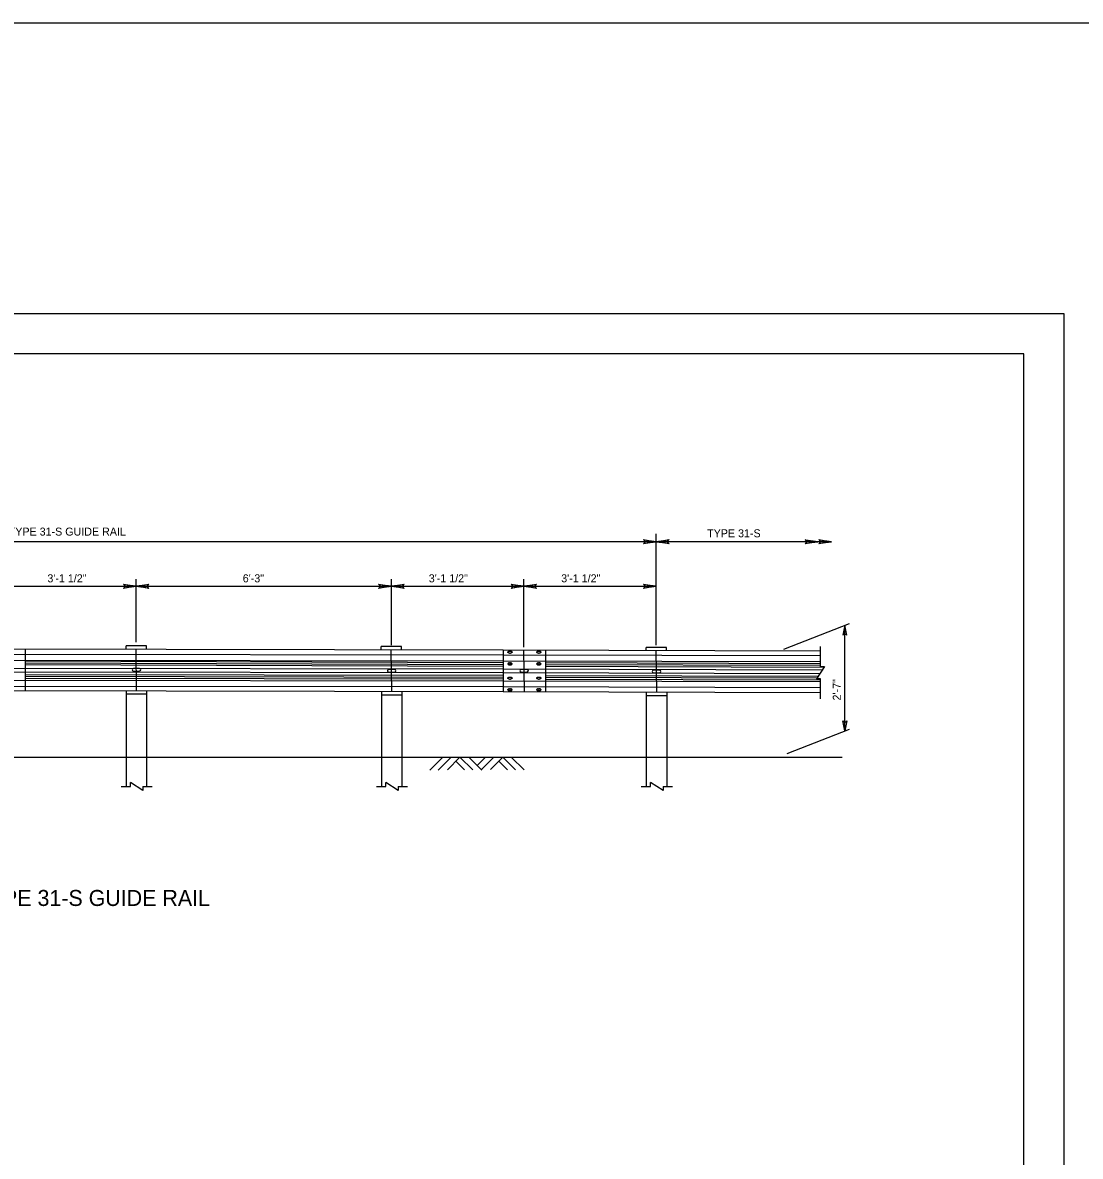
# Model space of a CAD drawing. Extents: x 637628 to 640188, y 298266 to 300751.
# Drawn here: x 639570.1 to 639966.7, y 300325.7 to 300750.7 of the extents above; entities that cross this region are included whole.
import ezdxf

# ---------------------------------------------------------------- set-up
doc = ezdxf.new("R2010")
doc.units = 0
for name, color, linetype in [('1', 7, 'Continuous'), ('2', 7, 'Continuous'), ('S-ABUT-CONC', 7, 'Continuous'), ('S-ANNO-CELL', 7, 'Continuous'), ('S-ANNO-DIMS-MANL', 7, 'Continuous'), ('S-ANNO-T120-01', 7, 'Continuous')]:
    doc.layers.add(name, color=color, linetype=linetype)

# ---------------------------------------------------------------- blocks, each defined once
blk = doc.blocks.new('LT')
at = {"layer": 'S-ANNO-DIMS-MANL'}
blk.add_lwpolyline([(0, 0), (-0.503, 0.094), (-0.464, 0.067), (-0.444, 0.034), (-0.439, 0), (-0.444, -0.034), (-0.464, -0.067), (-0.503, -0.094)], close=True, dxfattribs=at)

msp = doc.modelspace()

# ---------------------------------------------------------------- linework, layer by layer
at = {"layer": '1'}
msp.add_lwpolyline([(639119.52, 300641.58), (639960.52, 300641.58), (639960.52, 300047.58), (639119.52, 300047.58)], close=True, dxfattribs=at)
msp.add_lwpolyline([(639945.52, 300062.58), (639945.52, 300626.55), (639159.55, 300626.55), (639159.55, 300062.58), (639945.52, 300062.58), (639945.52, 300088.93), (639745.53, 300088.93), (639745.53, 300153.61), (639945.52, 300153.61), (639945.52, 300182.57), (639745.53, 300182.57), (639745.53, 300062.58), (639824.33, 300062.58), (639824.33, 300088.93), (639824.33, 300062.58), (639901.33, 300062.58), (639901.33, 300088.93), (639901.33, 300076.62), (639945.52, 300076.62)], dxfattribs=at)
at = {"layer": '2'}
for p, q in [((639727.59, 300475.23), (639722.82, 300470.46)), ((639730.7, 300475.23), (639725.92, 300470.46)), ((639734.11, 300475.36), (639729.38, 300470.63)), ((639735.77, 300470.59), (639732.55, 300473.81)), ((639738.88, 300470.59), (639734.11, 300475.36)), ((639742.29, 300470.46), (639737.56, 300475.19)), ((639743.71, 300475.33), (639740.57, 300472.18)), ((639746.82, 300475.33), (639742.05, 300470.56)), ((639750.13, 300475.36), (639745.5, 300470.73)), ((639751.9, 300470.6), (639748.68, 300473.82)), ((639754.91, 300470.59), (639750.13, 300475.36)), ((639758.15, 300470.56), (639753.35, 300475.36))]:
    msp.add_line(p, q, dxfattribs=at)
msp.add_lwpolyline([(638881.69, 300750.65), (640188.06, 300750.65), (640188.06, 299900.76), (638881.69, 299900.76)], close=True, dxfattribs=at)
for points in [[(639803.17, 300556.67), (639803.34, 300556.34), (639807.71, 300556.1), (639803.17, 300556.67), (639802.94, 300556.87), (639807.71, 300556.1), (639803.35, 300555.89), (639803.18, 300555.56), (639807.71, 300556.1), (639802.94, 300555.34), (639803.18, 300555.56)], [(639812.25, 300555.53), (639812.08, 300555.86), (639807.71, 300556.1), (639812.25, 300555.53), (639812.48, 300555.33), (639807.71, 300556.1), (639812.08, 300556.32), (639812.24, 300556.65), (639807.71, 300556.1), (639812.48, 300556.86), (639812.24, 300556.65)], [(639863.73, 300556.65), (639863.89, 300556.32), (639868.26, 300556.08), (639863.73, 300556.65), (639863.49, 300556.85), (639868.26, 300556.08), (639863.9, 300555.86), (639863.74, 300555.54), (639868.26, 300556.08), (639863.49, 300555.32), (639863.74, 300555.54)], [(639868.92, 300556.67), (639869.09, 300556.34), (639873.46, 300556.1), (639868.92, 300556.67), (639868.69, 300556.87), (639873.46, 300556.1), (639869.09, 300555.89), (639868.93, 300555.56), (639873.46, 300556.1), (639868.69, 300555.34), (639868.93, 300555.56)], [(639608.18, 300539.94), (639608.35, 300539.61), (639612.72, 300539.37), (639608.18, 300539.94), (639607.95, 300540.14), (639612.72, 300539.37), (639608.35, 300539.16), (639608.19, 300538.83), (639612.72, 300539.37), (639607.95, 300538.61), (639608.19, 300538.83)], [(639617.26, 300538.8), (639617.09, 300539.13), (639612.72, 300539.37), (639617.26, 300538.8), (639617.49, 300538.6), (639612.72, 300539.37), (639617.09, 300539.59), (639617.25, 300539.91), (639612.72, 300539.37), (639617.49, 300540.13), (639617.25, 300539.91)], [(639703.85, 300539.94), (639704.02, 300539.61), (639708.39, 300539.37), (639703.85, 300539.94), (639703.62, 300540.14), (639708.39, 300539.37), (639704.03, 300539.16), (639703.86, 300538.83), (639708.39, 300539.37), (639703.62, 300538.61), (639703.86, 300538.83)], [(639712.93, 300538.8), (639712.76, 300539.13), (639708.39, 300539.37), (639712.93, 300538.8), (639713.16, 300538.6), (639708.39, 300539.37), (639712.76, 300539.59), (639712.92, 300539.91), (639708.39, 300539.37), (639713.16, 300540.13), (639712.92, 300539.91)], [(639753.51, 300539.94), (639753.68, 300539.61), (639758.05, 300539.37), (639753.51, 300539.94), (639753.28, 300540.14), (639758.05, 300539.37), (639753.69, 300539.16), (639753.52, 300538.83), (639758.05, 300539.37), (639753.28, 300538.61), (639753.52, 300538.83)], [(639762.59, 300538.8), (639762.42, 300539.13), (639758.05, 300539.37), (639762.59, 300538.8), (639762.82, 300538.6), (639758.05, 300539.37), (639762.42, 300539.59), (639762.58, 300539.91), (639758.05, 300539.37), (639762.82, 300540.13), (639762.58, 300539.91)], [(639803.17, 300539.94), (639803.34, 300539.61), (639807.71, 300539.37), (639803.17, 300539.94), (639802.94, 300540.14), (639807.71, 300539.37), (639803.35, 300539.16), (639803.18, 300538.83), (639807.71, 300539.37), (639802.94, 300538.61), (639803.18, 300538.83)]]:
    msp.add_lwpolyline(points, dxfattribs=at)
at = {"layer": 'S-ABUT-CONC'}
for p, q in [((639807.71, 300517.3), (639807.71, 300559.09)), ((639807.71, 300556.1), (639562.85, 300556.1)), ((639873.46, 300556.1), (639807.71, 300556.1)), ((639612.72, 300518.38), (639612.72, 300542.08)), ((639708.39, 300517.88), (639708.39, 300542.08)), ((639708.39, 300517.25), (639708.39, 300542.08)), ((639758.05, 300516.51), (639758.05, 300542.08)), ((639562.85, 300539.37), (639660.56, 300539.37)), ((639660.56, 300539.37), (639708.39, 300539.37)), ((639708.39, 300539.37), (639758.05, 300539.37)), ((639758.05, 300539.37), (639807.71, 300539.37)), ((639855.56, 300515.85), (639880.18, 300525.46)), ((639878.42, 300485.14), (639878.42, 300524.77)), ((639856.74, 300476.67), (639880.18, 300485.83))]:
    msp.add_line(p, q, dxfattribs=at)
at = {"layer": 'S-ANNO-CELL'}
for p, q in [((639750.31, 300515.42), (639555.11, 300515.82)), ((639571.02, 300515.78), (639571.02, 300500.15)), ((639608.9, 300515.89), (639608.9, 300517.07)), ((639616.54, 300517.07), (639608.9, 300517.07)), ((639612.86, 300500.24), (639612.65, 300515.88)), ((639616.54, 300515.86), (639616.54, 300517.07)), ((639704.57, 300515.57), (639704.57, 300516.75)), ((639712.21, 300516.75), (639704.57, 300516.75)), ((639708.55, 300499.92), (639708.34, 300515.56)), ((639712.21, 300515.55), (639712.21, 300516.75)), ((639750.31, 300515.58), (639750.31, 300499.95)), ((639869.3, 300515.11), (639750.31, 300515.42)), ((639752.69, 300515.04), (639753.01, 300515.04)), ((639752.69, 300514.93), (639752.69, 300515.04)), ((639753.01, 300514.93), (639752.69, 300514.93)), ((639752.69, 300514.33), (639753.01, 300514.33)), ((639753.01, 300514.93), (639753.01, 300515.04)), ((639758.26, 300499.93), (639758.05, 300515.4)), ((639763.51, 300515.04), (639763.83, 300515.04)), ((639763.51, 300514.93), (639763.51, 300515.04)), ((639763.83, 300514.93), (639763.51, 300514.93)), ((639763.51, 300514.33), (639763.83, 300514.33)), ((639763.83, 300514.93), (639763.83, 300515.04)), ((639766.22, 300515.54), (639766.22, 300499.91)), ((639803.89, 300515.28), (639803.89, 300516.46)), ((639811.53, 300516.46), (639803.89, 300516.46)), ((639807.92, 300499.67), (639807.71, 300515.27)), ((639811.53, 300515.26), (639811.53, 300516.46)), ((639869.3, 300509.35), (639869.3, 300516.85)), ((639750.31, 300513.57), (639555.11, 300513.81)), ((639750.31, 300511.36), (639555.11, 300511.6)), ((639750.31, 300510.67), (639571.02, 300511.26)), ((639750.31, 300509.99), (639571.02, 300510.58)), ((639750.31, 300509.3), (639571.02, 300509.89)), ((639869.3, 300513.26), (639750.31, 300513.57)), ((639869.3, 300511.05), (639750.31, 300511.36)), ((639752.69, 300510.67), (639753.01, 300510.67)), ((639752.69, 300510.06), (639752.69, 300509.95)), ((639753.01, 300510.06), (639752.69, 300510.06)), ((639752.69, 300509.95), (639753.01, 300509.95)), ((639753.01, 300510.06), (639753.01, 300509.95)), ((639763.51, 300510.67), (639763.83, 300510.67)), ((639763.51, 300510.06), (639763.51, 300509.95)), ((639763.83, 300510.06), (639763.51, 300510.06)), ((639763.51, 300509.95), (639763.83, 300509.95)), ((639763.83, 300510.06), (639763.83, 300509.95)), ((639869.3, 300510.36), (639766.22, 300510.63)), ((639869.3, 300509.67), (639766.22, 300509.95)), ((639750.31, 300508.31), (639555.11, 300508.55)), ((639750.31, 300506.9), (639555.11, 300507.14)), ((639750.31, 300505.91), (639571.02, 300506.24)), ((639750.31, 300505.22), (639571.02, 300505.61)), ((639613.93, 300508.59), (639611.7, 300508.56)), ((639611.72, 300507.6), (639613.95, 300507.63)), ((639709.6, 300508.18), (639707.38, 300508.15)), ((639707.39, 300507.2), (639709.62, 300507.23)), ((639869.93, 300507.99), (639750.31, 300508.31)), ((639869.02, 300506.59), (639750.31, 300506.9)), ((639759.26, 300508.24), (639757.04, 300508.21)), ((639757.05, 300507.25), (639759.28, 300507.28)), ((639870.57, 300508.99), (639766.22, 300509.26)), ((639868.38, 300505.59), (639766.22, 300505.87)), ((639808.92, 300507.93), (639806.69, 300507.9)), ((639806.7, 300506.95), (639808.93, 300506.98)), ((639870.8, 300509.35), (639867.8, 300504.71)), ((639869.3, 300509.35), (639870.8, 300509.35)), ((639750.31, 300503.85), (639555.11, 300504.09)), ((639750.31, 300501.64), (639555.11, 300501.88)), ((639750.31, 300504.54), (639571.02, 300504.85)), ((639869.3, 300503.54), (639750.31, 300503.85)), ((639869.3, 300501.32), (639750.31, 300501.64)), ((639752.69, 300505.32), (639753.01, 300505.32)), ((639752.69, 300505.21), (639752.69, 300505.32)), ((639753.01, 300505.21), (639752.69, 300505.21)), ((639752.69, 300504.61), (639753.01, 300504.61)), ((639753.01, 300505.21), (639753.01, 300505.32)), ((639763.51, 300505.32), (639763.83, 300505.32)), ((639763.51, 300505.21), (639763.51, 300505.32)), ((639763.83, 300505.21), (639763.51, 300505.21)), ((639763.51, 300504.61), (639763.83, 300504.61)), ((639763.83, 300505.21), (639763.83, 300505.32)), ((639867.93, 300504.91), (639766.22, 300505.18)), ((639869.3, 300504.22), (639766.22, 300504.5)), ((639869.3, 300504.71), (639867.8, 300504.71)), ((639869.3, 300497.21), (639869.3, 300504.71)), ((639750.31, 300499.79), (639555.11, 300500.19)), ((639609.11, 300493.59), (639609.11, 300500.25)), ((639616.75, 300498.9), (639609.11, 300498.9)), ((639616.75, 300493.59), (639616.75, 300500.22)), ((639704.78, 300494.89), (639704.78, 300499.94)), ((639712.42, 300498.59), (639704.78, 300498.59)), ((639712.42, 300494.89), (639712.42, 300499.91)), ((639869.3, 300499.47), (639750.31, 300499.79)), ((639752.69, 300500.94), (639753.01, 300500.94)), ((639752.69, 300500.34), (639752.69, 300500.23)), ((639753.01, 300500.34), (639752.69, 300500.34)), ((639752.69, 300500.23), (639753.01, 300500.23)), ((639753.01, 300500.34), (639753.01, 300500.23)), ((639763.51, 300500.94), (639763.83, 300500.94)), ((639763.51, 300500.34), (639763.51, 300500.23)), ((639763.83, 300500.34), (639763.51, 300500.34)), ((639763.51, 300500.23), (639763.83, 300500.23)), ((639763.83, 300500.34), (639763.83, 300500.23)), ((639804.1, 300496.17), (639804.1, 300499.64)), ((639811.73, 300498.3), (639804.1, 300498.3)), ((639811.73, 300496.17), (639811.73, 300499.62)), ((639609.11, 300475.37), (639609.11, 300493.59)), ((639616.75, 300475.37), (639616.75, 300493.59)), ((639704.78, 300475.37), (639704.78, 300494.89)), ((639712.42, 300475.37), (639712.42, 300494.89)), ((639804.1, 300475.36), (639804.1, 300496.17)), ((639811.73, 300475.36), (639811.73, 300496.17)), ((639555.11, 300475.37), (639877.39, 300475.37)), ((639609.11, 300464.35), (639609.11, 300475.37)), ((639616.75, 300464.35), (639616.75, 300475.37)), ((639704.78, 300464.35), (639704.78, 300475.37)), ((639712.42, 300464.35), (639712.42, 300475.37)), ((639804.1, 300464.34), (639804.1, 300475.36)), ((639811.73, 300464.34), (639811.73, 300475.36)), ((639607.11, 300464.35), (639610.61, 300464.35)), ((639610.61, 300464.35), (639610.61, 300465.85)), ((639615.25, 300462.85), (639610.61, 300465.85)), ((639615.25, 300464.35), (639615.25, 300462.85)), ((639615.25, 300464.35), (639618.75, 300464.35)), ((639702.78, 300464.35), (639706.28, 300464.35)), ((639706.28, 300464.35), (639706.28, 300465.85)), ((639710.92, 300462.85), (639706.28, 300465.85)), ((639710.92, 300464.35), (639710.92, 300462.85)), ((639710.92, 300464.35), (639714.42, 300464.35)), ((639802.1, 300464.34), (639805.6, 300464.34)), ((639805.6, 300464.34), (639805.6, 300465.84)), ((639810.23, 300462.84), (639805.6, 300465.84)), ((639810.23, 300464.34), (639810.23, 300462.84)), ((639810.23, 300464.34), (639813.73, 300464.34))]:
    msp.add_line(p, q, dxfattribs=at)
for points in [[(639752.69, 300514.33), (639752.58, 300514.34), (639752.47, 300514.35), (639752.37, 300514.38), (639752.28, 300514.41), (639752.2, 300514.46), (639752.14, 300514.51), (639752.09, 300514.57), (639752.07, 300514.63), (639752.06, 300514.69), (639752.07, 300514.75), (639752.09, 300514.81), (639752.14, 300514.87), (639752.2, 300514.92), (639752.28, 300514.96), (639752.37, 300515), (639752.47, 300515.02), (639752.58, 300515.04), (639752.69, 300515.04)], [(639752.69, 300514.93), (639752.58, 300514.93), (639752.47, 300514.91), (639752.37, 300514.89), (639752.28, 300514.85), (639752.2, 300514.81), (639752.14, 300514.76), (639752.09, 300514.7), (639752.07, 300514.64), (639752.06, 300514.63)], [(639753.01, 300515.04), (639753.12, 300515.04), (639753.23, 300515.02), (639753.33, 300515), (639753.42, 300514.96), (639753.5, 300514.92), (639753.56, 300514.87), (639753.61, 300514.81), (639753.64, 300514.75), (639753.65, 300514.69), (639753.64, 300514.63), (639753.61, 300514.57), (639753.56, 300514.51), (639753.5, 300514.46), (639753.42, 300514.41), (639753.33, 300514.38), (639753.23, 300514.35), (639753.12, 300514.34), (639753.01, 300514.33)], [(639753.64, 300514.63), (639753.64, 300514.64), (639753.61, 300514.7), (639753.56, 300514.76), (639753.5, 300514.81), (639753.42, 300514.85), (639753.33, 300514.89), (639753.23, 300514.91), (639753.12, 300514.93), (639753.01, 300514.93)], [(639763.51, 300514.33), (639763.4, 300514.34), (639763.3, 300514.35), (639763.19, 300514.38), (639763.1, 300514.41), (639763.03, 300514.46), (639762.96, 300514.51), (639762.91, 300514.57), (639762.89, 300514.63), (639762.88, 300514.69), (639762.89, 300514.75), (639762.91, 300514.81), (639762.96, 300514.87), (639763.03, 300514.92), (639763.1, 300514.96), (639763.19, 300515), (639763.3, 300515.02), (639763.4, 300515.04), (639763.51, 300515.04)], [(639763.51, 300514.93), (639763.4, 300514.93), (639763.3, 300514.91), (639763.19, 300514.89), (639763.1, 300514.85), (639763.03, 300514.81), (639762.96, 300514.76), (639762.91, 300514.7), (639762.89, 300514.64), (639762.88, 300514.63)], [(639763.83, 300515.04), (639763.94, 300515.04), (639764.05, 300515.02), (639764.15, 300515), (639764.24, 300514.96), (639764.32, 300514.92), (639764.38, 300514.87), (639764.43, 300514.81), (639764.46, 300514.75), (639764.47, 300514.69), (639764.46, 300514.63), (639764.43, 300514.57), (639764.38, 300514.51), (639764.32, 300514.46), (639764.24, 300514.41), (639764.15, 300514.38), (639764.05, 300514.35), (639763.94, 300514.34), (639763.83, 300514.33)], [(639764.46, 300514.63), (639764.46, 300514.64), (639764.43, 300514.7), (639764.38, 300514.76), (639764.32, 300514.81), (639764.24, 300514.85), (639764.15, 300514.89), (639764.05, 300514.91), (639763.94, 300514.93), (639763.83, 300514.93)], [(639752.69, 300510.67), (639752.58, 300510.66), (639752.47, 300510.64), (639752.37, 300510.62), (639752.28, 300510.58), (639752.2, 300510.54), (639752.14, 300510.49), (639752.09, 300510.43), (639752.07, 300510.37), (639752.06, 300510.31), (639752.07, 300510.25), (639752.09, 300510.19), (639752.14, 300510.13), (639752.2, 300510.08), (639752.28, 300510.04), (639752.37, 300510), (639752.47, 300509.98), (639752.58, 300509.96), (639752.69, 300509.95)], [(639752.69, 300510.06), (639752.58, 300510.07), (639752.47, 300510.09), (639752.37, 300510.11), (639752.28, 300510.15), (639752.2, 300510.19), (639752.14, 300510.24), (639752.09, 300510.3), (639752.07, 300510.36), (639752.06, 300510.37)], [(639753.01, 300509.95), (639753.12, 300509.96), (639753.23, 300509.98), (639753.33, 300510), (639753.42, 300510.04), (639753.5, 300510.08), (639753.56, 300510.13), (639753.61, 300510.19), (639753.64, 300510.25), (639753.65, 300510.31), (639753.64, 300510.37), (639753.61, 300510.43), (639753.56, 300510.49), (639753.5, 300510.54), (639753.42, 300510.58), (639753.33, 300510.62), (639753.23, 300510.64), (639753.12, 300510.66), (639753.01, 300510.67)], [(639753.64, 300510.37), (639753.64, 300510.36), (639753.61, 300510.3), (639753.56, 300510.24), (639753.5, 300510.19), (639753.42, 300510.15), (639753.33, 300510.11), (639753.23, 300510.09), (639753.12, 300510.07), (639753.01, 300510.06)], [(639763.51, 300510.67), (639763.4, 300510.66), (639763.3, 300510.64), (639763.19, 300510.62), (639763.1, 300510.58), (639763.03, 300510.54), (639762.96, 300510.49), (639762.91, 300510.43), (639762.89, 300510.37), (639762.88, 300510.31), (639762.89, 300510.25), (639762.91, 300510.19), (639762.96, 300510.13), (639763.03, 300510.08), (639763.1, 300510.04), (639763.19, 300510), (639763.3, 300509.98), (639763.4, 300509.96), (639763.51, 300509.95)], [(639763.51, 300510.06), (639763.4, 300510.07), (639763.3, 300510.09), (639763.19, 300510.11), (639763.1, 300510.15), (639763.03, 300510.19), (639762.96, 300510.24), (639762.91, 300510.3), (639762.89, 300510.36), (639762.88, 300510.37)], [(639763.83, 300509.95), (639763.94, 300509.96), (639764.05, 300509.98), (639764.15, 300510), (639764.24, 300510.04), (639764.32, 300510.08), (639764.38, 300510.13), (639764.43, 300510.19), (639764.46, 300510.25), (639764.47, 300510.31), (639764.46, 300510.37), (639764.43, 300510.43), (639764.38, 300510.49), (639764.32, 300510.54), (639764.24, 300510.58), (639764.15, 300510.62), (639764.05, 300510.64), (639763.94, 300510.66), (639763.83, 300510.67)], [(639764.46, 300510.37), (639764.46, 300510.36), (639764.43, 300510.3), (639764.38, 300510.24), (639764.32, 300510.19), (639764.24, 300510.15), (639764.15, 300510.11), (639764.05, 300510.09), (639763.94, 300510.07), (639763.83, 300510.06)], [(639752.69, 300504.61), (639752.58, 300504.61), (639752.47, 300504.63), (639752.37, 300504.66), (639752.28, 300504.69), (639752.2, 300504.74), (639752.14, 300504.79), (639752.09, 300504.84), (639752.07, 300504.9), (639752.06, 300504.96), (639752.07, 300505.03), (639752.09, 300505.09), (639752.14, 300505.14), (639752.2, 300505.19), (639752.28, 300505.24), (639752.37, 300505.27), (639752.47, 300505.3), (639752.58, 300505.32), (639752.69, 300505.32)], [(639752.69, 300505.21), (639752.58, 300505.2), (639752.47, 300505.19), (639752.37, 300505.16), (639752.28, 300505.13), (639752.2, 300505.08), (639752.14, 300505.03), (639752.09, 300504.98), (639752.07, 300504.92), (639752.06, 300504.91)], [(639753.01, 300505.32), (639753.12, 300505.32), (639753.23, 300505.3), (639753.33, 300505.27), (639753.42, 300505.24), (639753.5, 300505.19), (639753.56, 300505.14), (639753.61, 300505.09), (639753.64, 300505.03), (639753.65, 300504.96), (639753.64, 300504.9), (639753.61, 300504.84), (639753.56, 300504.79), (639753.5, 300504.74), (639753.42, 300504.69), (639753.33, 300504.66), (639753.23, 300504.63), (639753.12, 300504.61), (639753.01, 300504.61)], [(639753.64, 300504.91), (639753.64, 300504.92), (639753.61, 300504.98), (639753.56, 300505.03), (639753.5, 300505.08), (639753.42, 300505.13), (639753.33, 300505.16), (639753.23, 300505.19), (639753.12, 300505.2), (639753.01, 300505.21)], [(639763.51, 300504.61), (639763.4, 300504.61), (639763.3, 300504.63), (639763.19, 300504.66), (639763.1, 300504.69), (639763.03, 300504.74), (639762.96, 300504.79), (639762.91, 300504.84), (639762.89, 300504.9), (639762.88, 300504.96), (639762.89, 300505.03), (639762.91, 300505.09), (639762.96, 300505.14), (639763.03, 300505.19), (639763.1, 300505.24), (639763.19, 300505.27), (639763.3, 300505.3), (639763.4, 300505.32), (639763.51, 300505.32)], [(639763.51, 300505.21), (639763.4, 300505.2), (639763.3, 300505.19), (639763.19, 300505.16), (639763.1, 300505.13), (639763.03, 300505.08), (639762.96, 300505.03), (639762.91, 300504.98), (639762.89, 300504.92), (639762.88, 300504.91)], [(639763.83, 300505.32), (639763.94, 300505.32), (639764.05, 300505.3), (639764.15, 300505.27), (639764.24, 300505.24), (639764.32, 300505.19), (639764.38, 300505.14), (639764.43, 300505.09), (639764.46, 300505.03), (639764.47, 300504.96), (639764.46, 300504.9), (639764.43, 300504.84), (639764.38, 300504.79), (639764.32, 300504.74), (639764.24, 300504.69), (639764.15, 300504.66), (639764.05, 300504.63), (639763.94, 300504.61), (639763.83, 300504.61)], [(639764.46, 300504.91), (639764.46, 300504.92), (639764.43, 300504.98), (639764.38, 300505.03), (639764.32, 300505.08), (639764.24, 300505.13), (639764.15, 300505.16), (639764.05, 300505.19), (639763.94, 300505.2), (639763.83, 300505.21)], [(639752.69, 300500.94), (639752.58, 300500.94), (639752.47, 300500.92), (639752.37, 300500.9), (639752.28, 300500.86), (639752.2, 300500.82), (639752.14, 300500.77), (639752.09, 300500.71), (639752.07, 300500.65), (639752.06, 300500.59), (639752.07, 300500.53), (639752.09, 300500.47), (639752.14, 300500.41), (639752.2, 300500.36), (639752.28, 300500.31), (639752.37, 300500.28), (639752.47, 300500.25), (639752.58, 300500.24), (639752.69, 300500.23)], [(639752.69, 300500.34), (639752.58, 300500.35), (639752.47, 300500.36), (639752.37, 300500.39), (639752.28, 300500.42), (639752.2, 300500.47), (639752.14, 300500.52), (639752.09, 300500.58), (639752.07, 300500.64), (639752.06, 300500.64)], [(639753.01, 300500.23), (639753.12, 300500.24), (639753.23, 300500.25), (639753.33, 300500.28), (639753.42, 300500.31), (639753.5, 300500.36), (639753.56, 300500.41), (639753.61, 300500.47), (639753.64, 300500.53), (639753.65, 300500.59), (639753.64, 300500.65), (639753.61, 300500.71), (639753.56, 300500.77), (639753.5, 300500.82), (639753.42, 300500.86), (639753.33, 300500.9), (639753.23, 300500.92), (639753.12, 300500.94), (639753.01, 300500.94)], [(639753.64, 300500.64), (639753.64, 300500.64), (639753.61, 300500.58), (639753.56, 300500.52), (639753.5, 300500.47), (639753.42, 300500.42), (639753.33, 300500.39), (639753.23, 300500.36), (639753.12, 300500.35), (639753.01, 300500.34)], [(639763.51, 300500.94), (639763.4, 300500.94), (639763.3, 300500.92), (639763.19, 300500.9), (639763.1, 300500.86), (639763.03, 300500.82), (639762.96, 300500.77), (639762.91, 300500.71), (639762.89, 300500.65), (639762.88, 300500.59), (639762.89, 300500.53), (639762.91, 300500.47), (639762.96, 300500.41), (639763.03, 300500.36), (639763.1, 300500.31), (639763.19, 300500.28), (639763.3, 300500.25), (639763.4, 300500.24), (639763.51, 300500.23)], [(639763.51, 300500.34), (639763.4, 300500.35), (639763.3, 300500.36), (639763.19, 300500.39), (639763.1, 300500.42), (639763.03, 300500.47), (639762.96, 300500.52), (639762.91, 300500.58), (639762.89, 300500.64), (639762.88, 300500.64)], [(639763.83, 300500.23), (639763.94, 300500.24), (639764.05, 300500.25), (639764.15, 300500.28), (639764.24, 300500.31), (639764.32, 300500.36), (639764.38, 300500.41), (639764.43, 300500.47), (639764.46, 300500.53), (639764.47, 300500.59), (639764.46, 300500.65), (639764.43, 300500.71), (639764.38, 300500.77), (639764.32, 300500.82), (639764.24, 300500.86), (639764.15, 300500.9), (639764.05, 300500.92), (639763.94, 300500.94), (639763.83, 300500.94)], [(639764.46, 300500.64), (639764.46, 300500.64), (639764.43, 300500.58), (639764.38, 300500.52), (639764.32, 300500.47), (639764.24, 300500.42), (639764.15, 300500.39), (639764.05, 300500.36), (639763.94, 300500.35), (639763.83, 300500.34)]]:
    msp.add_lwpolyline(points, dxfattribs=at)
for centre, start, end in [((639611.71, 300508.08), 90.7767, 270.7767), ((639613.94, 300508.11), 270.7767, 90.7767), ((639707.38, 300507.67), 90.7767, 270.7767), ((639709.61, 300507.7), 270.7767, 90.7767), ((639757.04, 300507.73), 90.7767, 270.7767), ((639759.27, 300507.76), 270.7767, 90.7767), ((639806.7, 300507.43), 90.7767, 270.7767), ((639808.92, 300507.46), 270.7767, 90.7767)]:
    msp.add_arc(centre, 0.477, start, end, dxfattribs=at)

# ---------------------------------------------------------------- block references
at = {"layer": 'S-ABUT-CONC'}
for p, xscale, yscale, rotation in [((639878.42, 300524.77), 7.4533753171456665, 7.9469763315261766, 90), ((639878.42, 300485.14), 7.453375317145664, -7.946976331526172, -90)]:
    msp.add_blockref('LT', p, dxfattribs=dict(at, xscale=xscale, yscale=yscale, rotation=rotation))

# ---------------------------------------------------------------- texts
for s, p in [('TYPE 2-WCC GUIDE RAIL HEIGHT TRANSITION TO TYPE 31-S GUIDE RAIL', (639466.85, 300558.38)), ('TYPE 31-S', (639826.78, 300557.75)), ('3\'-1 1/2"', (639579.41, 300540.87)), ('6\'-3"', (639652.66, 300540.87)), ('3\'-1 1/2"', (639722.4, 300540.87)), ('3\'-1 1/2"', (639772.06, 300540.87))]:
    msp.add_text(s, height=3, dxfattribs=at).set_placement(p)
msp.add_text('2\'-7"', height=3, rotation=90, dxfattribs=at).set_placement((639876.89, 300496.58))
at = {"layer": 'S-ANNO-T120-01'}
msp.add_text('TYPE 2-WCC GUIDE RAIL HEIGHT TRANSITION TO TYPE 31-S GUIDE RAIL', height=6, dxfattribs=at).set_placement((639356.39, 300419.55))

doc.saveas('drawing.dxf')
